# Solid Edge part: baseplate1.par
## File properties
Author: jmrobins
Template: sync iso part.par
Last saved by: mokuno
Revision: 19
Application: Solid Edge
Username: jmrobins
文書内容のタイプ: 0
Accuracy: 0.990
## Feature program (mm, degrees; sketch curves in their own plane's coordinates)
sketch for "unnamed Hole 1" plane through (5.246, 9.0254, 0) normal (0, 0, 1) x-axis (1, 0, 0)
  hole centre (-175.246, -59.0254) bore radius 10.376
hole "unnamed Hole 1" through
pattern "unnamed Pattern 1" of "unnamed Hole 1"
pattern "unnamed Pattern 2" of "unnamed Hole 1"
pattern "PatternOccurrence_1"  YCount = 2; XOffset = 340 mm; YOffset = 100 mm
sketch for "unnamed Hole 2" plane through (5.246, 109.0254, 0) normal (0, 0, 1) x-axis (1, 0, 0)
  hole centre (-175.246, -59.0254) bore radius 10.376
hole "unnamed Hole 2" through
sketch for "unnamed Hole 3" plane through (315.246, 9.0254, 0) normal (0, 0, 1) x-axis (1, 0, 0)
  hole centre (-175.246, -59.0254) bore radius 10.376
hole "unnamed Hole 3" through
sketch for "unnamed Hole 4" plane through (315.246, 109.0254, 0) normal (0, 0, 1) x-axis (1, 0, 0)
  hole centre (-175.246, -59.0254) bore radius 10.376
hole "unnamed Hole 4" through
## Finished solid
Body 1: solid body, 10 faces, 20 edges, 8 vertices.
  Faces by surface: plane 6, cylinder 4
  Edges by curve: line 12, circle 8
Bounding box of the edges (mm): 440.000 x 280.000 x 30.000, from (-220, -140, -30) to (220, 140, 0).
Cylindrical faces by radius (mm): R10.376 x4
Planar faces by outward normal: +x 1, +y 1, +z 1, -x 1, -y 1, -z 1
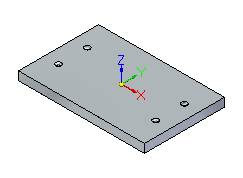
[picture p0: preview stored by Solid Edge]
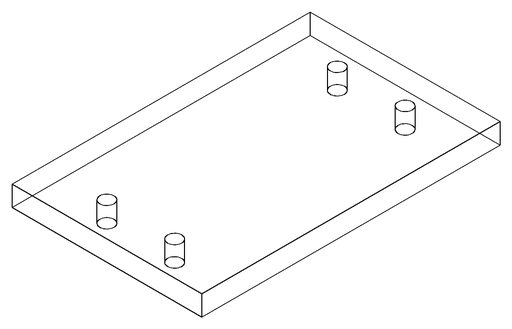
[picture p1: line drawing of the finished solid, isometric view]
